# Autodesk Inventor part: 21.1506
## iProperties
Created: 2006-12
Part Number: 21.1506
Material: Steel, Mild
Description: M6x16 C'SUNK
Document SubType Name: Modeling
Standard: DIN 7991
Designer: Andy Moles
Standards Organization: DIN
Language: en-US
Size Designation: M6x16
Categories: <MemberInstance Version="R10.0.0"><Categories><Category DisplayName="Fasteners" InternalName="e4da775c-781d-43d5-af7c-5136215cf5a6" Mnemonic="FSTN"><Category Di
Density: 7.86 g/cm^3
Mass: 4.35526 g
Surface Area: 5.4059 cm^2
Volume: 0.554104 cm^3
Vendor: S
Author: Andy Moles
Revision Number: 1
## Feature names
1. Revolution1
2. Extrusion1
3. Fillet1
4. Chamfer1
